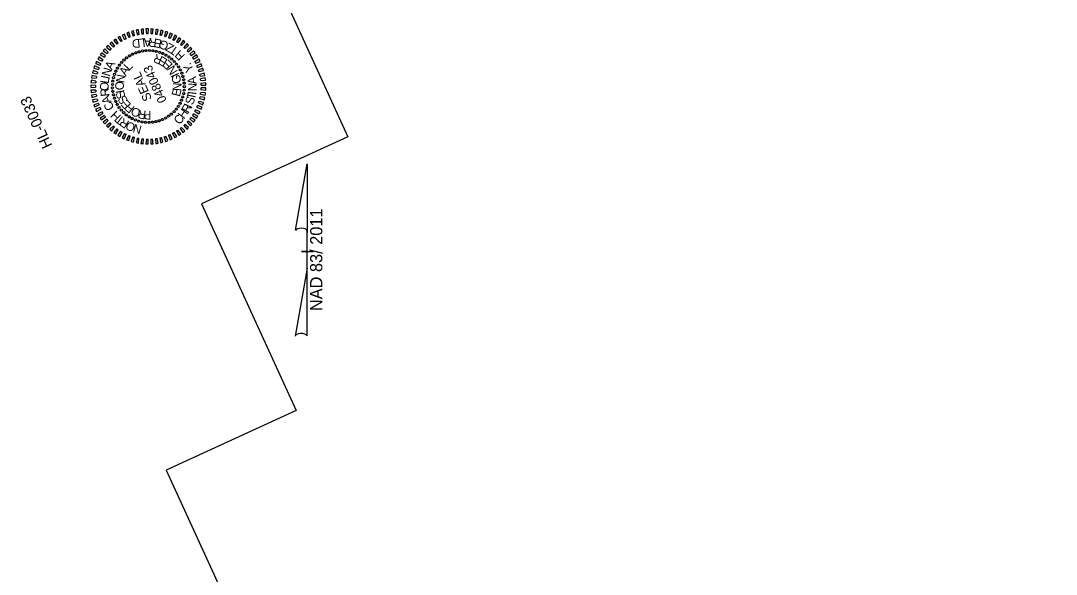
# Model space of a CAD drawing. Extents: x 2048005 to 2049520, y 757591 to 759287.
# Drawn here: x 2048043 to 2048763, y 758439 to 758824 of the extents above; entities that cross this region are included whole.
import ezdxf

# ---------------------------------------------------------------- set-up
doc = ezdxf.new("R2010")
doc.units = 0
for name, color, linetype in [('Prop North Arrow NAD83 for Plan Sheets CELL', 7, 'Continuous'), ('Sheet Clip Boundary CELL', 7, 'Continuous'), ('Sheet Data Field CELL', 7, 'Continuous'), ('Sheet PE Seal Cell', 7, 'Continuous')]:
    doc.layers.add(name, color=color, linetype=linetype)

msp = doc.modelspace()

# ---------------------------------------------------------------- linework, layer by layer
at = {"layer": 'Prop North Arrow NAD83 for Plan Sheets CELL'}
for p, q in [((2048233.61, 758678.05), (2048241.86, 758724.39)), ((2048241.91, 758724.39), (2048241.86, 758724.39)), ((2048241.91, 758724.39), (2048241.86, 758724.39)), ((2048241.91, 758724.39), (2048241.86, 758676.59)), ((2048241.83, 758651.79), (2048241.86, 758677.99)), ((2048241.86, 758676.59), (2048241.86, 758677.94)), ((2048237.84, 758663.39), (2048237.79, 758663.39)), ((2048241.39, 758663.39), (2048237.84, 758663.39)), ((2048237.89, 758663.39), (2048245.89, 758663.39)), ((2048241.83, 758651.79), (2048233.43, 758604.55)), ((2048241.83, 758604.74), (2048241.83, 758651.79))]:
    msp.add_line(p, q, dxfattribs=at)
for centre, start_param, end_param in [((2048237.75, 758677.55), 0.216388, 2.908219), ((2048237.67, 758604.38), 0.201328, 3.141593)]:
    msp.add_ellipse(centre, major_axis=(4.23, -0.03), ratio=0.461098, start_param=start_param, end_param=end_param, dxfattribs=at)
at = {"layer": 'Sheet Clip Boundary CELL'}
msp.add_lwpolyline([(2048565.47, 757590.62), (2049520.08, 758027.9), (2048982.56, 759201.34), (2048218.78, 758855.25), (2048270.17, 758743.08), (2048168.29, 758696.41), (2048234.11, 758552.71), (2048143.72, 758511.31)], close=True, dxfattribs=at)
at = {"layer": 'Sheet PE Seal Cell'}
for p, q in [((2048124.96, 758814.16), (2048124.56, 758817.49)), ((2048126.33, 758817.76), (2048126.94, 758814.46)), ((2048128.08, 758814.58), (2048127.97, 758817.93)), ((2048129.76, 758818.05), (2048130.08, 758814.71)), ((2048131.23, 758814.73), (2048131.41, 758818.08)), ((2048133.21, 758818.04), (2048133.24, 758814.68)), ((2048134.38, 758814.61), (2048134.85, 758817.93)), ((2048136.63, 758817.74), (2048136.38, 758814.39)), ((2048137.51, 758814.22), (2048138.27, 758817.49)), ((2048110.5, 758808.17), (2048108.75, 758811.04)), ((2048110.25, 758812.02), (2048112.17, 758809.27)), ((2048113.16, 758809.86), (2048111.66, 758812.86)), ((2048113.24, 758813.71), (2048114.92, 758810.81)), ((2048115.96, 758811.31), (2048114.73, 758814.43)), ((2048116.37, 758815.14), (2048117.8, 758812.11)), ((2048118.87, 758812.52), (2048117.91, 758815.73)), ((2048119.61, 758816.3), (2048120.77, 758813.15)), ((2048121.88, 758813.47), (2048121.2, 758816.75)), ((2048122.94, 758817.17), (2048123.83, 758813.94)), ((2048140.02, 758817.14), (2048139.48, 758813.83)), ((2048140.6, 758813.56), (2048141.63, 758816.75)), ((2048143.35, 758816.26), (2048142.52, 758813.01)), ((2048143.61, 758812.64), (2048144.91, 758815.73)), ((2048146.59, 758815.09), (2048145.48, 758811.92)), ((2048146.54, 758811.46), (2048148.1, 758814.43)), ((2048149.71, 758813.65), (2048148.34, 758810.59)), ((2048149.35, 758810.04), (2048151.16, 758812.86)), ((2048152.7, 758811.94), (2048151.07, 758809.01)), ((2048152.03, 758808.38), (2048154.08, 758811.04)), ((2048103.5, 758801.83), (2048101.08, 758804.15)), ((2048102.28, 758805.49), (2048104.85, 758803.32)), ((2048105.65, 758804.14), (2048103.44, 758806.66)), ((2048104.74, 758807.89), (2048107.11, 758805.51)), ((2048107.99, 758806.26), (2048106, 758808.96)), ((2048107.41, 758810.07), (2048109.56, 758807.5)), ((2048155.54, 758809.99), (2048153.66, 758807.21)), ((2048154.56, 758806.5), (2048156.83, 758808.97)), ((2048158.19, 758807.8), (2048156.08, 758805.19)), ((2048156.92, 758804.4), (2048159.39, 758806.67)), ((2048160.65, 758805.39), (2048158.32, 758802.97)), ((2048159.09, 758802.11), (2048161.75, 758804.16)), ((2048096.25, 758797.14), (2048099.28, 758795.7)), ((2048099.85, 758796.7), (2048097.06, 758798.57)), ((2048098.02, 758800.09), (2048100.91, 758798.4)), ((2048101.57, 758799.35), (2048098.95, 758801.45)), ((2048100.03, 758802.88), (2048102.77, 758800.95)), ((2048162.88, 758802.77), (2048160.36, 758800.56)), ((2048161.05, 758799.64), (2048163.88, 758801.45)), ((2048164.89, 758799.98), (2048162.19, 758797.99)), ((2048162.8, 758797.02), (2048165.77, 758798.58)), ((2048166.65, 758797.02), (2048163.78, 758795.27)), ((2048096.14, 758788.02), (2048092.97, 758789.12)), ((2048093.5, 758790.83), (2048096.74, 758789.94)), ((2048097.13, 758791.02), (2048094.06, 758792.39)), ((2048094.74, 758794.04), (2048097.88, 758792.87)), ((2048098.36, 758793.92), (2048095.43, 758795.54)), ((2048164.31, 758794.25), (2048167.4, 758795.55)), ((2048168.15, 758793.92), (2048165.14, 758792.43)), ((2048165.58, 758791.36), (2048168.77, 758792.39)), ((2048169.37, 758790.7), (2048166.25, 758789.47)), ((2048166.59, 758788.37), (2048169.86, 758789.13)), ((2048094.96, 758781.83), (2048091.65, 758782.37)), ((2048091.88, 758784.15), (2048095.22, 758783.82)), ((2048095.42, 758784.95), (2048092.16, 758785.78)), ((2048092.55, 758787.53), (2048095.85, 758786.91)), ((2048170.32, 758787.39), (2048167.1, 758786.44)), ((2048167.35, 758785.31), (2048170.67, 758785.78)), ((2048170.97, 758784.01), (2048167.69, 758783.34)), ((2048167.83, 758782.2), (2048171.18, 758782.38)), ((2048091.42, 758777.29), (2048094.77, 758777.54)), ((2048094.77, 758778.69), (2048091.43, 758778.94)), ((2048091.5, 758780.73), (2048094.86, 758780.69)), ((2048094.85, 758775.53), (2048091.5, 758775.5)), ((2048091.64, 758773.85), (2048094.95, 758774.39)), ((2048131.42, 758778.08), (2048131.42, 758778.08)), ((2048171.34, 758780.59), (2048168, 758780.2)), ((2048168, 758775.9), (2048171.33, 758775.5)), ((2048168.05, 758779.05), (2048171.41, 758778.94)), ((2048171.41, 758777.15), (2048168.05, 758777.05)), ((2048095.21, 758772.4), (2048091.87, 758772.08)), ((2048092.15, 758770.45), (2048095.4, 758771.27)), ((2048095.83, 758769.31), (2048092.53, 758768.7)), ((2048092.95, 758767.1), (2048096.12, 758768.2)), ((2048169.84, 758766.97), (2048166.57, 758767.73)), ((2048167.09, 758769.66), (2048170.3, 758768.7)), ((2048170.65, 758770.31), (2048167.33, 758770.79)), ((2048167.68, 758772.76), (2048170.96, 758772.08)), ((2048171.18, 758773.72), (2048167.83, 758773.9)), ((2048096.72, 758766.28), (2048093.48, 758765.39)), ((2048094.04, 758763.84), (2048097.1, 758765.2)), ((2048097.86, 758763.34), (2048094.71, 758762.18)), ((2048095.4, 758760.68), (2048098.34, 758762.3)), ((2048099.25, 758760.51), (2048096.22, 758759.08)), ((2048163.76, 758760.83), (2048166.62, 758759.08)), ((2048167.37, 758760.55), (2048164.28, 758761.86)), ((2048165.12, 758763.68), (2048168.12, 758762.18)), ((2048168.74, 758763.71), (2048165.55, 758764.74)), ((2048166.23, 758766.63), (2048169.35, 758765.39)), ((2048097.03, 758757.64), (2048099.82, 758759.51)), ((2048100.88, 758757.81), (2048097.98, 758756.12)), ((2048098.91, 758754.76), (2048101.53, 758756.86)), ((2048102.74, 758755.26), (2048099.99, 758753.33)), ((2048101.04, 758752.06), (2048103.47, 758754.37)), ((2048104.8, 758752.88), (2048102.24, 758750.72)), ((2048158.28, 758753.15), (2048160.6, 758750.72)), ((2048161.7, 758751.95), (2048159.05, 758754)), ((2048160.32, 758755.55), (2048162.84, 758753.34)), ((2048163.84, 758754.65), (2048161.02, 758756.47)), ((2048162.15, 758758.12), (2048164.85, 758756.13)), ((2048165.73, 758757.53), (2048162.76, 758759.09)), ((2048103.39, 758749.54), (2048105.61, 758752.06)), ((2048107.07, 758750.69), (2048104.7, 758748.31)), ((2048105.95, 758747.24), (2048107.94, 758749.94)), ((2048109.51, 758748.69), (2048107.35, 758746.13)), ((2048108.69, 758745.16), (2048110.45, 758748.02)), ((2048112.12, 758746.92), (2048110.19, 758744.18)), ((2048111.61, 758743.33), (2048113.11, 758746.33)), ((2048148.29, 758745.54), (2048149.65, 758742.48)), ((2048151.11, 758743.26), (2048149.3, 758746.09)), ((2048151.02, 758747.12), (2048152.65, 758744.18)), ((2048154.03, 758745.08), (2048151.98, 758747.75)), ((2048153.61, 758748.92), (2048155.48, 758746.13)), ((2048156.78, 758747.15), (2048154.52, 758749.63)), ((2048156.04, 758750.93), (2048158.14, 758748.32)), ((2048159.35, 758749.44), (2048156.88, 758751.72)), ((2048114.87, 758745.38), (2048113.18, 758742.48)), ((2048114.67, 758741.76), (2048115.9, 758744.87)), ((2048117.74, 758744.08), (2048116.31, 758741.04)), ((2048117.85, 758740.45), (2048118.82, 758743.66)), ((2048120.72, 758743.03), (2048119.55, 758739.88)), ((2048121.14, 758739.42), (2048121.82, 758742.71)), ((2048123.77, 758742.24), (2048122.88, 758739)), ((2048124.5, 758738.68), (2048124.9, 758742.01)), ((2048126.88, 758741.71), (2048126.27, 758738.41)), ((2048127.91, 758738.23), (2048128.02, 758741.59)), ((2048130.02, 758741.46), (2048129.7, 758738.12)), ((2048131.35, 758738.08), (2048131.17, 758741.43)), ((2048133.18, 758741.47), (2048133.14, 758738.12)), ((2048134.79, 758738.22), (2048134.32, 758741.55)), ((2048136.32, 758741.76), (2048136.57, 758738.41)), ((2048138.2, 758738.66), (2048137.45, 758741.93)), ((2048139.42, 758742.31), (2048139.96, 758739)), ((2048141.56, 758739.39), (2048140.54, 758742.58)), ((2048142.47, 758743.14), (2048143.29, 758739.88)), ((2048144.85, 758740.4), (2048143.56, 758743.5)), ((2048145.43, 758744.21), (2048146.53, 758741.04)), ((2048148.04, 758741.7), (2048146.48, 758744.67))]:
    msp.add_line(p, q, dxfattribs=at)
for radius, start, end in [(40, 99.86677, 102.23039), (40, 94.93526, 97.29888), (40, 90.00376, 92.36738), (40, 85.07225, 87.43587), (40, 80.14074, 82.50436), (40, 124.5243, 126.88792), (40, 119.5928, 121.95642), (40, 114.66129, 117.02491), (36.65, 114.94415, 116.74205), (40, 109.72978, 112.0934), (36.65, 110.01265, 111.81054), (40, 104.79828, 107.1619), (36.65, 105.08114, 106.87903), (36.65, 100.14963, 101.94753), (36.65, 95.21813, 97.01602), (36.65, 90.28662, 92.08451), (36.65, 85.35511, 87.15301), (36.65, 80.4236, 82.2215), (36.65, 75.4921, 77.28999), (40, 75.20924, 77.57285), (36.65, 70.56059, 72.35849), (40, 70.27773, 72.64135), (36.65, 65.62908, 67.42698), (40, 65.34622, 67.70984), (36.65, 60.69758, 62.49547), (40, 60.41472, 62.77833), (40, 55.48321, 57.84683), (40, 139.31883, 141.68244), (40, 134.38732, 136.75094), (40, 129.45581, 131.81943), (36.65, 134.67018, 136.46808), (36.65, 129.73867, 131.53657), (36.65, 124.80717, 126.60506), (36.65, 119.87566, 121.67355), (36.65, 55.76607, 57.56397), (36.65, 50.83456, 52.63246), (40, 50.5517, 52.91532), (36.65, 45.90306, 47.70095), (40, 45.6202, 47.98381), (40, 40.68869, 43.05231), (40, 149.18184, 151.54546), (40, 144.25033, 146.61395), (36.65, 149.4647, 151.2626), (36.65, 144.53319, 146.33109), (36.65, 139.60169, 141.39958), (36.65, 40.97155, 42.76944), (36.65, 36.04004, 37.83794), (36.65, 31.10854, 32.90643), (40, 35.75718, 38.1208), (40, 30.82567, 33.18929), (40, 25.89417, 28.25779), (40, 163.97636, 166.33998), (40, 159.04485, 161.40847), (40, 154.11335, 156.47696), (36.65, 159.32771, 161.12561), (36.65, 154.39621, 156.1941), (36.65, 26.17703, 27.97492), (36.65, 21.24552, 23.04342), (36.65, 16.31402, 18.11191), (40, 20.96266, 23.32628), (40, 16.03115, 18.39477), (40, 173.83937, 176.20299), (40, 168.90787, 171.27148), (36.65, 174.12223, 175.92013), (36.65, 169.19073, 170.98862), (36.65, 164.25922, 166.05712), (36.65, 11.38251, 13.1804), (36.65, 6.451, 8.2489), (40, 11.09965, 13.46327), (40, 6.16814, 8.53176), (40, 178.77088, 181.1345), (40, 183.70239, 186.06601), (36.65, 179.05374, 180.85164), (36.65, 183.98525, 185.78314), (36.65, 1.5195, 3.31739), (36.65, 356.58799, 358.38588), (40, 356.30513, 358.66875), (40, 1.23663, 3.60025), (40, 188.63389, 190.99751), (40, 193.5654, 195.92902), (36.65, 188.91676, 190.71465), (36.65, 193.84826, 195.64616), (36.65, 341.79347, 343.59136), (36.65, 346.72497, 348.52287), (36.65, 351.65648, 353.45438), (40, 346.44211, 348.80573), (40, 351.37362, 353.73724), (40, 198.49691, 200.86053), (40, 203.42841, 205.79203), (36.65, 198.77977, 200.57766), (36.65, 203.71128, 205.50917), (36.65, 208.64278, 210.44068), (36.65, 331.93045, 333.72835), (36.65, 336.86196, 338.65986), (40, 331.64759, 334.01121), (40, 336.5791, 338.94272), (40, 341.51061, 343.87422), (40, 208.35992, 210.72354), (40, 213.29143, 215.65505), (40, 218.22293, 220.58655), (36.65, 213.57429, 215.37218), (36.65, 218.5058, 220.30369), (36.65, 223.4373, 225.2352), (36.65, 317.13593, 318.93383), (36.65, 322.06744, 323.86534), (36.65, 326.99895, 328.79684), (40, 321.78458, 324.1482), (40, 326.71609, 329.0797), (40, 223.15444, 225.51806), (40, 228.08595, 230.44957), (36.65, 228.36881, 230.16671), (40, 233.01746, 235.38107), (36.65, 233.30032, 235.09821), (36.65, 238.23182, 240.02972), (36.65, 297.40991, 299.2078), (36.65, 302.34141, 304.13931), (36.65, 307.27292, 309.07081), (40, 306.99006, 309.35368), (36.65, 312.20443, 314.00232), (40, 311.92156, 314.28518), (40, 316.85307, 319.21669), (40, 237.94896, 240.31258), (40, 242.88047, 245.24409), (36.65, 243.16333, 244.96123), (40, 247.81198, 250.17559), (36.65, 248.09484, 249.89273), (40, 252.74348, 255.1071), (36.65, 253.02634, 254.82424), (40, 257.67499, 260.03861), (36.65, 257.95785, 259.75575), (40, 262.6065, 264.97011), (36.65, 262.88936, 264.68725), (36.65, 267.82087, 269.61876), (36.65, 272.75237, 274.55027), (36.65, 277.68388, 279.48177), (40, 277.40102, 279.76464), (36.65, 282.61539, 284.41328), (40, 282.33252, 284.69614), (36.65, 287.54689, 289.34479), (40, 287.26403, 289.62765), (36.65, 292.4784, 294.27629), (40, 292.19554, 294.55916), (40, 297.12704, 299.49066), (40, 302.05855, 304.42217), (40, 267.538, 269.90162), (40, 272.46951, 274.83313)]:
    msp.add_arc((2048131.42, 758778.08), radius, start, end, dxfattribs=at)
for centre, major_axis in [((2048124.98, 758802.24), (-0.241, 0.702)), ((2048127.34, 758802.75), (-0.172, 0.722)), ((2048129.74, 758803.02), (-0.101, 0.735)), ((2048132.16, 758803.07), (-0.03, 0.742)), ((2048134.56, 758802.88), (0.042, 0.741)), ((2048136.94, 758802.46), (0.113, 0.734)), ((2048114.49, 758796.48), (-0.539, 0.51)), ((2048116.35, 758798.03), (-0.488, 0.56)), ((2048118.34, 758799.39), (-0.431, 0.604)), ((2048120.46, 758800.55), (-0.371, 0.643)), ((2048122.68, 758801.5), (-0.307, 0.676)), ((2048139.27, 758801.81), (0.184, 0.719)), ((2048141.53, 758800.94), (0.252, 0.698)), ((2048143.68, 758799.86), (0.318, 0.671)), ((2048145.73, 758798.58), (0.382, 0.637)), ((2048147.64, 758797.1), (0.441, 0.597)), ((2048149.4, 758795.44), (0.497, 0.552)), ((2048108.8, 758788.74), (-0.692, 0.269)), ((2048109.94, 758790.87), (-0.663, 0.334)), ((2048111.27, 758792.88), (-0.627, 0.397)), ((2048112.79, 758794.76), (-0.586, 0.456)), ((2048150.99, 758793.63), (0.548, 0.501)), ((2048152.4, 758791.67), (0.593, 0.446)), ((2048153.62, 758789.58), (0.634, 0.387)), ((2048106.7, 758781.83), (-0.74, 0.06)), ((2048107.18, 758784.2), (-0.731, 0.131)), ((2048107.88, 758786.51), (-0.715, 0.201)), ((2048154.62, 758787.38), (0.668, 0.324)), ((2048155.41, 758785.1), (0.696, 0.258)), ((2048155.98, 758782.75), (0.718, 0.189)), ((2048106.44, 758777.01), (-0.738, -0.083)), ((2048106.45, 758779.42), (-0.742, -0.012)), ((2048106.66, 758774.6), (-0.726, -0.154)), ((2048156.31, 758780.36), (0.733, 0.119)), ((2048156.29, 758775.53), (0.742, -0.024)), ((2048156.42, 758777.94), (0.741, 0.048)), ((2048107.11, 758772.23), (-0.708, -0.224)), ((2048107.79, 758769.91), (-0.683, -0.291)), ((2048108.69, 758767.67), (-0.652, -0.355)), ((2048153.49, 758766.34), (0.678, -0.302)), ((2048154.52, 758768.53), (0.704, -0.235)), ((2048155.33, 758770.8), (0.724, -0.166)), ((2048155.92, 758773.14), (0.736, -0.095)), ((2048109.8, 758765.52), (-0.614, -0.417)), ((2048111.11, 758763.5), (-0.571, -0.474)), ((2048112.61, 758761.6), (-0.523, -0.527)), ((2048114.29, 758759.87), (-0.47, -0.575)), ((2048149.21, 758760.52), (0.563, -0.483)), ((2048150.82, 758762.32), (0.607, -0.427)), ((2048152.25, 758764.27), (0.646, -0.366)), ((2048116.13, 758758.3), (-0.412, -0.618)), ((2048118.11, 758756.92), (-0.35, -0.654)), ((2048120.21, 758755.73), (-0.286, -0.685)), ((2048122.42, 758754.75), (-0.218, -0.71)), ((2048124.72, 758753.99), (-0.149, -0.727)), ((2048127.07, 758753.46), (-0.078, -0.738)), ((2048129.47, 758753.16), (-0.006, -0.742)), ((2048131.88, 758753.08), (0.066, -0.739)), ((2048134.29, 758753.25), (0.137, -0.73)), ((2048136.68, 758753.64), (0.206, -0.713)), ((2048139.01, 758754.26), (0.274, -0.69)), ((2048141.27, 758755.11), (0.34, -0.66)), ((2048143.45, 758756.16), (0.402, -0.624)), ((2048145.51, 758757.43), (0.46, -0.583)), ((2048147.43, 758758.88), (0.514, -0.535))]:
    msp.add_ellipse(centre, major_axis=major_axis, ratio=0.999708, dxfattribs=at)

# ---------------------------------------------------------------- texts
at = {"layer": 'Prop North Arrow NAD83 for Plan Sheets CELL'}
msp.add_text('NAD 83/ 2011', height=8.5, rotation=89.93911, dxfattribs=at).set_placement((2048252.32, 758621.86))
at = {"layer": 'Sheet Data Field CELL'}
msp.add_text('HL-0033', height=7.5, rotation=114.57389, dxfattribs=at).set_placement((2048064.85, 758737.05))
at = {"layer": 'Sheet PE Seal Cell'}
for s, height, rotation, p in [('D', 6, 186.66229, (2048125.45, 758811.24)), ('L', 6, 186.66229, (2048128.96, 758811.65)), ('A', 6, 180.54613, (2048133.5, 758811.73)), ('R', 6, 173.72376, (2048137.48, 758811.24)), ('E', 6, 167.14918, (2048141.24, 758810.33)), ('G', 6, 158.15863, (2048146.16, 758808.4)), ('Z', 6, 151.19171, (2048149.73, 758806.38)), ('T', 6, 144.82362, (2048152.76, 758804.18)), ('I', 6, 140.45852, (2048154.68, 758802.48)), ('R', 6, 157.60789, (2048141.8, 758798.68)), ('E', 6, 148.85489, (2048145.3, 758796.53)), ('E', 6, 132.45124, (2048148.78, 758793.16)), ('F', 6, 133.94588, (2048157.3, 758799.68)), ('N', 6, 72.21724, (2048104.49, 758784.56)), ('A', 6, 63.28691, (2048106.12, 758789.26)), ('A', 6, 57.83195, (2048115.73, 758785.06)), ('L', 6, 47.69888, (2048118.03, 758788.62)), ('048043', 6.185, 113.61022, (2048144.34, 758768.2)), ('N', 6, 121.60204, (2048152.03, 758788.47)), ('Y', 6, 113.67493, (2048163.18, 758789.37)), ('.', 6, 120.7864, (2048161.54, 758793.22)), ('L', 6, 82.04135, (2048103.78, 758779.8)), ('I', 6, 78.05369, (2048104.2, 758782.85)), ('N', 6, 80.35233, (2048114.57, 758780.2)), ('SEAL', 6.184, 113.61022, (2048134.07, 758769.43)), ('I', 6, 114.15248, (2048152.99, 758786.14)), ('G', 6, 98.56782, (2048154.28, 758780.52)), ('A', 6, 97.30448, (2048165.07, 758779.96)), ('O', 6, 89.24164, (2048103.78, 758774.96)), ('R', 6, 96.53088, (2048104.44, 758771.46)), ('O', 6, 92.06578, (2048114.5, 758775.6)), ('I', 6, 100.45566, (2048114.9, 758773.95)), ('S', 6, 114.61559, (2048115.98, 758771.06)), ('E', 6, 76.18456, (2048153.26, 758770.64)), ('N', 6, 86.03809, (2048154.24, 758774.75)), ('T', 6, 77.58074, (2048163.73, 758768.49)), ('I', 6, 83.94883, (2048164.6, 758772.13)), ('N', 6, 88.31394, (2048164.95, 758774.67)), ('A', 6, 112.01811, (2048105.94, 758767.5)), ('C', 6, 120.9025, (2048108.02, 758763.44)), ('S', 6, 122.99577, (2048117.65, 758768.08)), ('E', 6, 131.79489, (2048119.85, 758765.51)), ('S', 6, 70.86162, (2048162.39, 758764.77)), ('H', 6, 135.27137, (2048112.87, 758757.58)), ('F', 6, 140.0221, (2048122.37, 758763.52)), ('O', 6, 158.96977, (2048126.57, 758761.74)), ('R', 6, 170.89606, (2048130.21, 758761.06)), ('P', 6, 179.40332, (2048133.5, 758761.08)), ('H', 6, 53.84629, (2048156.21, 758755.02)), ('R', 6, 59.67413, (2048159.22, 758759.01)), ('I', 6, 66.49651, (2048161.29, 758762.45)), ('T', 6, 141.66452, (2048115.28, 758755.62)), ('R', 6, 148.76145, (2048118.58, 758753.56)), ('O', 6, 156.42405, (2048123, 758751.63)), ('C', 6, 53.84629, (2048153.37, 758751.12)), ('N', 6, 165.44384, (2048127.28, 758750.63))]:
    msp.add_text(s, height=height, rotation=rotation, dxfattribs=at).set_placement(p)

doc.saveas('drawing.dxf')
